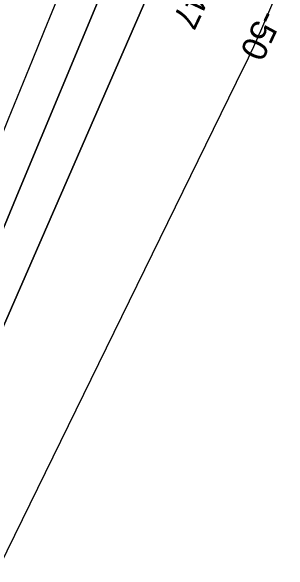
# Model space of a CAD drawing. Extents: x 3923531 to 3943530, y 207391 to 229799.
# Drawn here: x 3936536 to 3936907, y 221544 to 222290 of the extents above; entities that cross this region are included whole.
import ezdxf

# ---------------------------------------------------------------- set-up
doc = ezdxf.new("R2010")
doc.units = 0
for name, color, linetype in [('V-RIVR-RANG', 7, 'Continuous'), ('V-TOPO-DPTH', 7, 'Continuous'), ('V-TOPO-MAJR', 7, 'Continuous'), ('V-TOPO-MINR', 7, 'Continuous')]:
    doc.layers.add(name, color=color, linetype=linetype)

msp = doc.modelspace()

# ---------------------------------------------------------------- linework, layer by layer
at = {"layer": 'V-TOPO-DPTH'}
for points in [[(3936610.81, 222338.44), (3936580.27, 222263.3), (3936564.33, 222224.17), (3936548.36, 222185.06), (3936532.33, 222145.97), (3936516.26, 222106.9), (3936348.61, 221700.12), (3936329.02, 221653.95), (3936308.8, 221608.07), (3936287.63, 221562.61), (3936265.84, 221517.45), (3936256.97, 221499.54), (3936237.37, 221464.85), (3936215.49, 221431.86), (3935792.56, 220666.96)], [(3935868.43, 220706.48), (3936232.07, 221305.79), (3936262.13, 221372.01), (3936270.55, 221390.79), (3936278.85, 221409.62), (3936286.98, 221428.52), (3936294.99, 221447.47), (3936368.79, 221624.41), (3936413.62, 221731.86), (3936458.46, 221839.31), (3936503.32, 221946.76), (3936548.18, 222054.2), (3936658.19, 222317.62)], [(3935868.43, 220706.48), (3936232.07, 221305.79), (3936262.13, 221372.01), (3936270.55, 221390.79), (3936278.85, 221409.62), (3936286.98, 221428.52), (3936294.99, 221447.47), (3936368.79, 221624.41), (3936413.62, 221731.86), (3936458.46, 221839.31), (3936503.32, 221946.76), (3936548.18, 222054.2), (3936658.19, 222317.62)], [(3936715.87, 222305.18), (3936408.67, 221602.31), (3936393.94, 221568.48), (3936379.26, 221534.62), (3936364.67, 221500.73), (3936350.15, 221466.81), (3936335.59, 221432.9), (3936320.93, 221399.04), (3936306.13, 221365.24), (3936291.23, 221331.48), (3935982.21, 220682.3)], [(3935982.21, 220682.3), (3936291.23, 221331.48), (3936306.13, 221365.24), (3936320.93, 221399.04), (3936335.59, 221432.9), (3936350.15, 221466.81), (3936364.67, 221500.73), (3936379.26, 221534.62), (3936393.94, 221568.48), (3936408.67, 221602.31), (3936715.87, 222305.18)]]:
    msp.add_lwpolyline(points, dxfattribs=at)
at = {"layer": 'V-TOPO-MAJR'}
msp.add_lwpolyline([(3936951.98, 222457.78), (3936868.87, 222263.2), (3936866.25, 222257.15), (3936863.6, 222251.12), (3936860.88, 222245.11), (3936858.13, 222239.13), (3936855.33, 222233.16), (3936852.51, 222227.21), (3936849.64, 222221.27), (3936846.76, 222215.35), (3936427.82, 221362.35), (3936425.74, 221358.11), (3936423.67, 221353.88), (3936421.6, 221349.64), (3936419.54, 221345.4), (3936336.91, 221174.92), (3936294.13, 221085.17)], dxfattribs=at)
at = {"layer": 'V-TOPO-MINR'}
for points in [[(3936610.81, 222338.44), (3936580.27, 222263.3), (3936564.33, 222224.17), (3936548.36, 222185.06), (3936532.33, 222145.97), (3936516.26, 222106.9), (3936348.61, 221700.12), (3936329.02, 221653.95), (3936308.8, 221608.07), (3936287.63, 221562.61), (3936265.84, 221517.45), (3936256.97, 221499.54), (3936237.37, 221464.85), (3936215.49, 221431.86), (3935792.56, 220666.96)], [(3936658.19, 222317.62), (3936548.18, 222054.2), (3936503.32, 221946.76), (3936458.46, 221839.31), (3936413.62, 221731.86), (3936368.79, 221624.41), (3936294.99, 221447.47), (3936286.98, 221428.52), (3936278.85, 221409.62), (3936270.55, 221390.79), (3936262.13, 221372.01), (3936232.07, 221305.79), (3935868.43, 220706.48)], [(3936715.87, 222305.18), (3936408.67, 221602.31), (3936393.94, 221568.48), (3936379.26, 221534.62), (3936364.67, 221500.73), (3936350.15, 221466.81), (3936335.59, 221432.9), (3936320.93, 221399.04), (3936306.13, 221365.24), (3936291.23, 221331.48), (3935982.21, 220682.3)]]:
    msp.add_lwpolyline(points, dxfattribs=at)

# ---------------------------------------------------------------- texts
at = {"layer": 'V-RIVR-RANG'}
for s, p in [('-47', (3936777.93, 222335.45)), ('-50', (3936868.55, 222293.67))]:
    msp.add_text(s, height=33.5, rotation=244.79467, dxfattribs=at).set_placement(p)

doc.saveas('drawing.dxf')
